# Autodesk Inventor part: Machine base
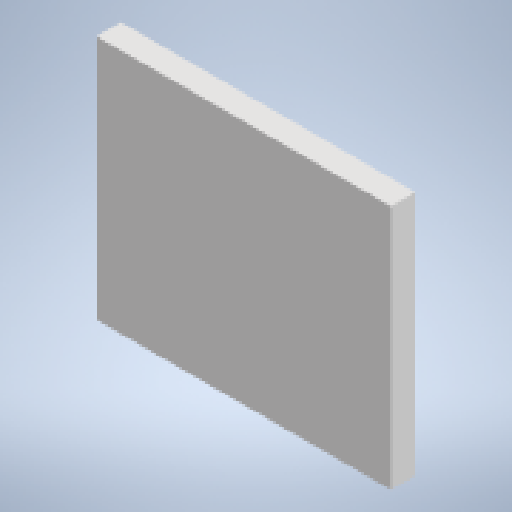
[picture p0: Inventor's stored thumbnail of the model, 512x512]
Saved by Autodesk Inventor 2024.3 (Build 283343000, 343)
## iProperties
Created: 2024-12
Part Number: Machine base
Material: Generic
Document SubType Name: Modeling
Designer: ruhr
Density: 1 g/cm^3
Appearance: Default
Author: ruhr
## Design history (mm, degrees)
sketch "Sketch1"
  geometry: L1 (-120, 100)-(120, 100); L2 (120, 100)-(120, -100); L3 (120, -100)-(-120, -100); L4 (-120, -100)-(-120, 100); L5 (-120, 100)-(120, -100); L6 (120, 100)-(-120, -100); 1 further point
  constraints: 12 end point, 2 midpoint, 2 parallel, 1 horizontal, 1 perpendicular
  dimensions: "d0" = 240 distance of L2.end L3.end; "d1" = 200 distance of L1.end L2.end
extrude "Extrusion1" new body sketch "Sketch1" distance "d2" = 20; taper "d3" = 0 deg
body "Solid1"
